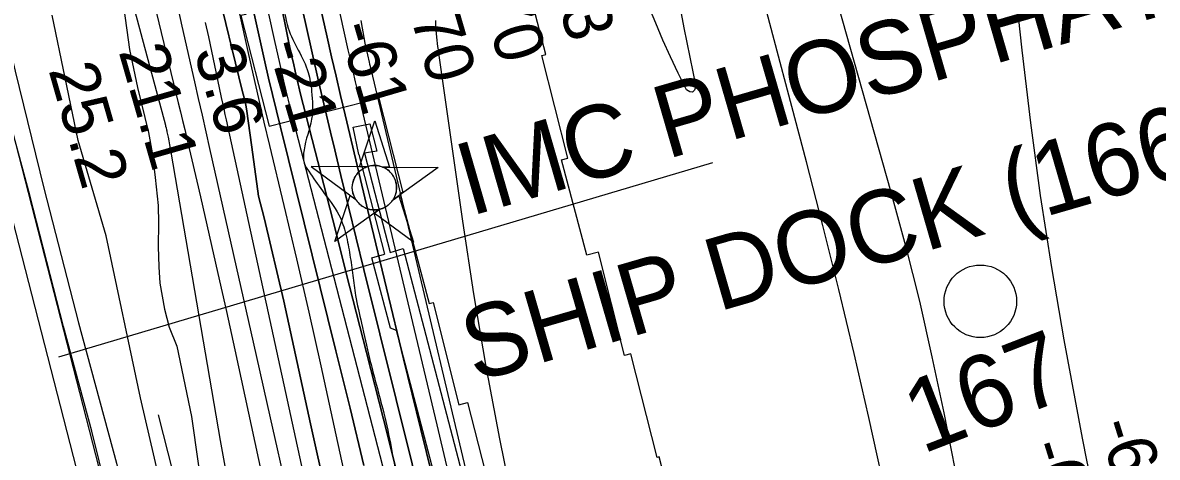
# Model space of a CAD drawing. Extents: x 3405885 to 3443815, y 558517 to 583997.
# Drawn here: x 3413052 to 3414615, y 578768 to 579366 of the extents above; entities that cross this region are included whole.
import ezdxf

# ---------------------------------------------------------------- set-up
doc = ezdxf.new("R2010")
doc.units = 0
for name, color, linetype in [('V-CHAN-DOCK', 7, 'Continuous'), ('V-CHAN-NAID', 7, 'Continuous'), ('V-FLOD-BASE', 7, 'Continuous'), ('V-LEVE-TOET', 7, 'Continuous'), ('V-RIVR-EDGE', 7, 'Continuous'), ('V-RIVR-IDEN', 7, 'Continuous'), ('V-RIVR-MILE', 7, 'Continuous'), ('V-RIVR-RANG', 7, 'Continuous'), ('V-RRAP-RVMT', 7, 'Continuous'), ('V-SITE-VEGE', 7, 'Continuous'), ('V-SURV-LINE', 7, 'Continuous'), ('V-TOPO-DPTH', 7, 'Continuous'), ('V-TOPO-MAJR', 7, 'Continuous'), ('V-TOPO-MINR', 7, 'Continuous'), ('V-TOPO-WATR', 7, 'Continuous')]:
    doc.layers.add(name, color=color, linetype=linetype)

msp = doc.modelspace()

# ---------------------------------------------------------------- linework, layer by layer
at = {"layer": 'V-CHAN-DOCK'}
for p, q in [((3413515.1, 579185), (3413550.3, 579047.6)), ((3413523, 579186.4), (3413558, 579049.8))]:
    msp.add_line(p, q, dxfattribs=at)
for points in [[(3413515.1, 579185), (3413507.4, 579222.2), (3413530.3, 579227.2), (3413539.7, 579189.4), (3413523, 579186.4)], [(3413558, 579049.8), (3413576.3, 579055.1), (3413724.6, 578488.5), (3413706.9, 578484.5)], [(3413267, 578487.6), (3413647.8, 578585.7), (3413627.3, 578663.7), (3413637.3, 578674.7), (3413566.8, 578942.3), (3413558.6, 578945.8), (3413532.9, 579042.5), (3413550.3, 579047.6)]]:
    msp.add_lwpolyline(points, dxfattribs=at)
at = {"layer": 'V-CHAN-NAID'}
for points in [[(3413525.6, 579167.6), (3413516.1, 579167.7), (3413537.2, 579231.2), (3413557.4, 579167.4), (3413547.8, 579167.5), (3413546.2, 579168), (3413544.1, 579168.7), (3413542.1, 579169.1), (3413540.1, 579169.4), (3413538.9, 579169.5), (3413537.4, 579169.6), (3413535.6, 579169.6), (3413534.3, 579169.5), (3413532.4, 579169.3), (3413531, 579169.1), (3413529.2, 579168.7), (3413527.7, 579168.3), (3413526.7, 579168)], [(3413525.6, 579167.6), (3413449.2, 579168.2), (3413510.7, 579122.8), (3413509.6, 579124.7), (3413508.8, 579126.3), (3413508, 579128.3), (3413507.3, 579130.3), (3413506.9, 579131.6), (3413506.5, 579133.3), (3413506.3, 579134.7), (3413506.1, 579136.3), (3413506, 579138), (3413506, 579139.6), (3413506.1, 579141.7), (3413506.3, 579143.3), (3413506.7, 579145.5), (3413507.2, 579147.4), (3413507.8, 579149.3), (3413508.4, 579151), (3413509.1, 579152.6), (3413510, 579154.1), (3413511, 579155.9), (3413512, 579157.3), (3413513, 579158.6), (3413514.1, 579159.8), (3413515.4, 579161.1), (3413516.4, 579162.1), (3413518.1, 579163.5), (3413519.3, 579164.3), (3413521, 579165.4), (3413522.8, 579166.3), (3413524.2, 579167)], [(3413547.8, 579167.5), (3413624.3, 579166.9), (3413562.1, 579122.4), (3413563, 579123.9), (3413564, 579125.7), (3413564.7, 579127.3), (3413565.5, 579129.3), (3413566, 579131.1), (3413566.4, 579132.7), (3413566.8, 579134.7), (3413566.9, 579136.3), (3413567.1, 579138.5), (3413567, 579140.5), (3413566.8, 579142.8), (3413566.6, 579144.5), (3413566.1, 579146.8), (3413565.5, 579148.9), (3413564.7, 579150.9), (3413564.1, 579152.3), (3413563, 579154.2), (3413562, 579156), (3413560.8, 579157.7), (3413559.5, 579159.2), (3413558.2, 579160.6), (3413556.6, 579162.1), (3413554.9, 579163.5), (3413553.2, 579164.7), (3413551.3, 579165.8), (3413549.8, 579166.6)], [(3413544.1, 579109.5), (3413481.9, 579065), (3413503, 579128.4), (3413510.7, 579122.8), (3413511.4, 579121.8), (3413512.7, 579119.9), (3413513.9, 579118.5), (3413515.4, 579117), (3413516.8, 579115.8), (3413518.3, 579114.6), (3413519.7, 579113.6), (3413521.3, 579112.6), (3413523.1, 579111.7), (3413524.8, 579110.9), (3413526.3, 579110.3), (3413527.9, 579109.8), (3413530.1, 579109.2), (3413531.7, 579108.9), (3413533.7, 579108.7), (3413535.2, 579108.6), (3413537.1, 579108.5), (3413538.8, 579108.6), (3413540.5, 579108.8), (3413542.4, 579109.1)], [(3413562.1, 579122.4), (3413569.9, 579128), (3413590.1, 579064.2), (3413536.3, 579103.9), (3413544.1, 579109.5), (3413545.7, 579110), (3413547.4, 579110.5), (3413549.5, 579111.4), (3413551.2, 579112.3), (3413553.1, 579113.4), (3413554.9, 579114.6), (3413556.4, 579115.9), (3413557.7, 579117.1), (3413559.1, 579118.5), (3413560.3, 579119.9), (3413561.4, 579121.4)]]:
    msp.add_lwpolyline(points, close=True, dxfattribs=at)
msp.add_circle((3413536.5, 579139.1), 30.5, dxfattribs=at)
at = {"layer": 'V-FLOD-BASE'}
msp.add_lwpolyline([(3413465.8, 577560.7), (3413432.4, 577685.7), (3413392.9, 577856.9), (3413362.4, 577972.1), (3413330.7, 578093.7), (3413298, 578218.3), (3413261.7, 578356.5), (3413239.3, 578440.4), (3413213.9, 578520.8), (3413187.5, 578640.5), (3413147.2, 578803.6), (3413108.1, 578947.7), (3413061.5, 579129), (3413012.6, 579309.2), (3412974.9, 579462.8), (3412927.8, 579646.5), (3412885.9, 579814.8), (3412853.9, 579977.7), (3412809.2, 580169), (3412768.3, 580316.1)], dxfattribs=at)
at = {"layer": 'V-LEVE-TOET'}
msp.add_lwpolyline([(3412767.9, 580481), (3412806.4, 580341.6), (3412860.6, 580143.7), (3412871.5, 580101.8), (3412901.2, 579957.1), (3412913, 579869.8), (3412926, 579791.3), (3412952.9, 579666.1), (3412992.6, 579509), (3413041.3, 579299.4), (3413080.9, 579138.2), (3413128.6, 578952.8), (3413181, 578759.6), (3413225.8, 578579.5), (3413232.6, 578542.3)], dxfattribs=at)
at = {"layer": 'V-RIVR-EDGE'}
msp.add_spline([(3412820.9, 582098.3), (3412817.8, 582058), (3412815.6, 582029.5), (3412817.7, 582007.9), (3412825.7, 581980.1), (3412850.3, 581879.9), (3412863.7, 581832.7), (3412872, 581799.1), (3412892.3, 581722.3), (3412903.2, 581678.4), (3412909.6, 581634.8), (3412920.5, 581599), (3412934, 581569.3), (3412943.4, 581548.5), (3412954.7, 581511.2), (3412955.3, 581484.9), (3412959.7, 581464), (3412965.1, 581459.6), (3412977.9, 581445), (3412992.4, 581409.1), (3413006.5, 581353.1), (3413015.2, 581302.3), (3413018.7, 581260.3), (3413013.9, 581236.1), (3413008.8, 581220.1), (3413005.1, 581206.5), (3413003.6, 581194.5), (3413004.7, 581180.2), (3413009.3, 581149.1), (3413020.6, 581117.3), (3413042, 581073), (3413073, 581031.3), (3413081, 581018.1), (3413088.7, 580999.8), (3413094.4, 580977.9), (3413100.2, 580939.1), (3413102.7, 580912), (3413106.3, 580894.1), (3413113.5, 580861.9), (3413124.8, 580824.3), (3413140, 580781.4), (3413146.5, 580756.9), (3413148.7, 580740.1), (3413153.8, 580721.8), (3413161, 580692.6), (3413184.2, 580615.7), (3413194, 580582.5), (3413204.2, 580568.2), (3413207.8, 580561.6), (3413214, 580535.3), (3413232.1, 580461.7), (3413244, 580397.7), (3413253, 580345.1), (3413251.9, 580330.8), (3413256.4, 580258.4), (3413262.5, 580217.5), (3413264.6, 580175.4), (3413271.5, 580146.5), (3413278.7, 580117.3), (3413280.2, 580104.8), (3413276.4, 580060.6), (3413276.3, 580025.9), (3413275.6, 580012.4), (3413275.5, 580006.1), (3413277.7, 580003.2), (3413288, 580000.6), (3413298.6, 579998.4), (3413303.7, 579992.2), (3413305.5, 579985.2), (3413310.1, 579953.8), (3413314.5, 579931.1), (3413321, 579914.6), (3413327.2, 579894.5), (3413327.1, 579868.9), (3413323.4, 579842.6), (3413317.9, 579835.3), (3413316, 579824.7), (3413315.6, 579806.5), (3413320, 579780.1), (3413328, 579765.1), (3413335.6, 579758.2), (3413338.2, 579753.4), (3413338.9, 579747.5), (3413338.9, 579742.8), (3413335.5, 579730.7), (3413330.8, 579723.1), (3413327.8, 579714.3), (3413325.2, 579701.2), (3413326.7, 579689.5), (3413332.1, 579675.9), (3413338.3, 579668.2), (3413342.7, 579666.4), (3413352.6, 579666.7), (3413357.3, 579663.4), (3413365.3, 579652.4), (3413371.9, 579635.2), (3413374.8, 579618.4), (3413377.6, 579592.5), (3413379.4, 579557.4), (3413373.8, 579521.6), (3413375.2, 579501.1), (3413382.1, 579476.9), (3413395.1, 579440), (3413408.6, 579400.8), (3413417.6, 579358.8), (3413445.2, 579297.7), (3413449.9, 579271.7), (3413449.8, 579233.3), (3413439.5, 579191.3), (3413438.7, 579182.2), (3413439.8, 579172.7), (3413446, 579161.7), (3413464.9, 579134.6), (3413487.5, 579101.6), (3413497, 579074.9), (3413502.7, 579046.4), (3413506.7, 579018.2), (3413510.6, 578990.8), (3413518.6, 578952.4), (3413529.8, 578903.8), (3413538.1, 578871.6), (3413547.9, 578834.6), (3413558.4, 578787.4), (3413566.7, 578743.2), (3413574.6, 578699.3), (3413585.1, 578637.1), (3413595.2, 578577.2), (3413599.5, 578547.5), (3413610.7, 578516.1), (3413620.2, 578504), (3413626, 578499.2), (3413635.5, 578497), (3413635.9, 578494.4), (3413634.1, 578490.1), (3413632.2, 578487.1), (3413632.2, 578479.5), (3413633.2, 578455), (3413642.2, 578391), (3413644.3, 578359.2), (3413649, 578338.7), (3413656.3, 578322.2), (3413667.6, 578313.8), (3413676, 578309), (3413684.4, 578305.3), (3413688.8, 578300.2), (3413697.9, 578288.5), (3413702.2, 578272.4), (3413709.1, 578250.8), (3413714.9, 578233.2), (3413728.7, 578187.2), (3413734.8, 578151.3), (3413738.8, 578114.4), (3413740.5, 578084), (3413746.7, 578059.2), (3413750.7, 578043.4), (3413751.3, 578020), (3413747.6, 577990.8), (3413742, 577955), (3413736.9, 577934.5), (3413735.4, 577919.6), (3413733.5, 577904.2), (3413737.1, 577880.1), (3413741.4, 577864.7), (3413741.4, 577863.2), (3413750.2, 577865.8), (3413755, 577862.8), (3413760, 577845.7), (3413773.8, 577798.1), (3413781.8, 577765.2), (3413793, 577724.9), (3413797, 577700.4), (3413803.4, 577637.2), (3413804.4, 577613.8), (3413807.7, 577591.8), (3413815.3, 577561.1), (3413829.4, 577524.9), (3413841.8, 577493.8), (3413853.8, 577466), (3413863.2, 577445.5), (3413869.8, 577431.2), (3413869.8, 577426.1), (3413869.7, 577412.9), (3413868.9, 577389.5), (3413869.2, 577353), (3413871, 577339.8), (3413873.9, 577328.5), (3413883, 577306.5), (3413889.5, 577287.9), (3413905.1, 577244.3), (3413913.5, 577211), (3413925.4, 577161.3), (3413947.6, 577101.7), (3413958.8, 577073.5), (3413969, 577057.4), (3413973, 577043.8), (3413979.9, 577014.6), (3414002, 576930.8), (3414004.5, 576907.4), (3414006.3, 576897.2), (3414015, 576880.3), (3414024.5, 576858.8), (3414031.3, 576835.7), (3414040.8, 576799.5), (3414054.2, 576750.1), (3414062.5, 576713.9), (3414069.3, 576679.9), (3414074.4, 576668.5), (3414075.1, 576663.4), (3414103.1, 576586.2), (3414107.4, 576564.6), (3414115.4, 576529.2), (3414119, 576508), (3414142.2, 576433.7), (3414153.5, 576399.3), (3414159.6, 576378.5), (3414164.7, 576348.8), (3414174.1, 576303.8), (3414178, 576275), (3414184.1, 576248.3), (3414191.1, 576234), (3414204.1, 576202.1), (3414212.1, 576179.5), (3414243, 576089.5), (3414264.8, 576025.4), (3414269.5, 576005.7), (3414269.4, 575994.4), (3414267.6, 575989.1)], degree=3, dxfattribs=at)
at = {"layer": 'V-RIVR-MILE'}
msp.add_circle((3414371.4, 578982.6), 50, dxfattribs=at)
at = {"layer": 'V-RIVR-RANG'}
msp.add_line((3413101.6, 578906), (3414002.6, 579173.9), dxfattribs=at)
at = {"layer": 'V-RRAP-RVMT'}
for points in [[(3413113.3, 580352.9), (3413130.9, 580232.1), (3413110.9, 580229.3), (3413132.9, 580079.4), (3413115.1, 580075.8), (3413143.9, 579932.2), (3413132.9, 579930.1), (3413162.8, 579777.1), (3413165.6, 579777.6), (3413194.6, 579633.9), (3413200, 579635), (3413229.1, 579491.8), (3413325, 579511.4), (3413341.4, 579447.3), (3413441.1, 579472.8), (3413451.2, 579433.2), (3413351.8, 579407), (3413359.3, 579377.6), (3413352.6, 579376), (3413391.4, 579223.8), (3413542.6, 579262.3), (3413575.6, 579132.6)], [(3413803, 579179.7), (3413767, 579320.9), (3413772.6, 579322.3), (3413733.3, 579474.4), (3413717.6, 579470.3), (3413688.3, 579584), (3413727.7, 579592), (3413696.4, 579745.4), (3413681.1, 579742.3), (3413652.2, 579885.5), (3413624, 579880), (3413596.2, 580022.5), (3413563.4, 580016.3), (3413534.8, 580159.2), (3413519.8, 580156.2), (3413500.9, 580285.6)], [(3413993.1, 578375.8), (3413970.6, 578464.8), (3414002.6, 578473), (3413965.8, 578615.9), (3413968.5, 578616.6), (3413929, 578768.5), (3413926.3, 578767.7), (3413889.9, 578910.4), (3413880.9, 578908.1), (3413845.2, 579050.3), (3413829.2, 579046.3), (3413794.4, 579177.6), (3413803, 579179.7)], [(3413575.6, 579132.6), (3413571.6, 579131.6), (3413611.8, 578979.7), (3413617.4, 578981.1), (3413652.8, 578840.1), (3413664.8, 578843.1), (3413699.3, 578708.7), (3413688.9, 578706.1), (3413728, 578555.6), (3413730.8, 578556.3), (3413767.7, 578413.3), (3413769.5, 578413.8), (3413778.5, 578378.1)]]:
    msp.add_lwpolyline(points, dxfattribs=at)
at = {"layer": 'V-SITE-VEGE'}
for points in [[(3413185.3, 579429.3), (3413198.8, 579329.5), (3413210.2, 579277), (3413225.1, 579214.9), (3413230.3, 579187.2), (3413234.2, 579153), (3413238.6, 579114.6), (3413239.1, 579090.4), (3413238.3, 579058), (3413239.3, 579030.2), (3413240.9, 579007.8), (3413247.1, 578971.8), (3413253.5, 578947), (3413264.2, 578920.7), (3413284.2, 578823.9), (3413302.8, 578694.6)], [(3413252.6, 578683.7), (3413214.1, 578849.7), (3413166.7, 579073), (3413128, 579204.1), (3413092.6, 579376.6)]]:
    msp.add_lwpolyline(points, dxfattribs=at)
at = {"layer": 'V-SURV-LINE'}
for points in [[(3412864.6, 579889.2), (3413603.1, 577015.1)], [(3413574.1, 577007.7), (3412835.6, 579881.8)]]:
    msp.add_lwpolyline(points, dxfattribs=at)
at = {"layer": 'V-TOPO-DPTH'}
for points in [[(3413113.8, 580487.8), (3413186.9, 580114.7), (3413203.7, 580017.6), (3413234.8, 579843), (3413255.8, 579718.6), (3413318.1, 579422.2), (3413354.3, 579273.1), (3413358.5, 579257.7), (3413360.2, 579247.5), (3413367.7, 579194.7), (3413376.9, 579127.4), (3413384.5, 579097.6), (3413411.5, 578982.6), (3413448.5, 578813.9), (3413532.7, 578434.8), (3413535.3, 578425.5), (3413536.9, 578418.7), (3413621.2, 578042.1), (3413698.7, 577706.5), (3413704.6, 577683.5), (3413708.8, 577666.4), (3413718.9, 577631.5), (3413770.4, 577445.8)], [(3413770.4, 577445.8), (3413718.9, 577631.5), (3413708.8, 577666.4), (3413704.6, 577683.5), (3413698.7, 577706.5), (3413621.2, 578042.1), (3413536.9, 578418.7), (3413535.3, 578425.5), (3413532.7, 578434.8), (3413448.5, 578813.9), (3413411.5, 578982.6), (3413384.5, 579097.6), (3413376.9, 579127.4), (3413367.7, 579194.7), (3413360.2, 579247.5), (3413358.5, 579257.7), (3413354.3, 579273.1), (3413318.1, 579422.2), (3413255.8, 579718.6), (3413234.8, 579843), (3413203.7, 580017.6), (3413186.9, 580114.7), (3413113.8, 580487.8)], [(3413654.9, 578491), (3413521.9, 579026.6), (3413511.2, 579069.7), (3413500.7, 579112.9), (3413490.3, 579156), (3413479.9, 579199.2), (3413477.9, 579207.8), (3413468.7, 579246.8), (3413459.6, 579285.7), (3413450.6, 579324.7), (3413441.8, 579363.7), (3413402.4, 579539.5)], [(3413654.9, 578491), (3413521.9, 579026.6), (3413511.2, 579069.7), (3413500.7, 579112.9), (3413490.3, 579156), (3413479.9, 579199.2), (3413477.9, 579207.8), (3413468.7, 579246.8), (3413459.6, 579285.7), (3413450.6, 579324.7), (3413441.8, 579363.7), (3413402.4, 579539.5)], [(3413451.1, 579436.2), (3413471.4, 579346.2), (3413477.5, 579319.4), (3413483.6, 579292.7), (3413489.8, 579266), (3413496.1, 579239.3), (3413529.8, 579098), (3413553.1, 579000.7), (3413576.5, 578903.4), (3413600.2, 578806.2), (3413624.1, 578709)], [(3413451.1, 579436.2), (3413471.4, 579346.2), (3413477.5, 579319.4), (3413483.6, 579292.7), (3413489.8, 579266), (3413496.1, 579239.3), (3413529.8, 579098), (3413553.1, 579000.7), (3413576.5, 578903.4), (3413600.2, 578806.2), (3413624.1, 578709)], [(3413257.9, 579422.9), (3413271.3, 579361.6), (3413288.5, 579285), (3413293.7, 579262.1), (3413298.9, 579239.1), (3413304.1, 579216.2), (3413309.2, 579193.2), (3413346.1, 579030.2), (3413369.5, 578926.3), (3413392.9, 578822.3), (3413416.2, 578718.3)], [(3413369, 579386.8), (3413385.6, 579312.3), (3413390.7, 579289.8), (3413396, 579267.3), (3413401.4, 579244.8), (3413406.9, 579222.4), (3413483.5, 578914.5), (3413502.9, 578835.6), (3413521.7, 578756.6)], [(3413521.7, 578756.6), (3413502.9, 578835.6), (3413483.5, 578914.5), (3413406.9, 579222.4), (3413401.4, 579244.8), (3413396, 579267.3), (3413390.7, 579289.8), (3413385.6, 579312.3), (3413369, 579386.8)], [(3413571.9, 578728.8), (3413548.8, 578820.3), (3413525.6, 578911.9), (3413502.3, 579003.4), (3413479, 579094.9), (3413434.2, 579269.8), (3413433.2, 579273.8), (3413432.2, 579277.8), (3413431.3, 579281.8), (3413430.4, 579285.8), (3413427.3, 579299.5), (3413424.8, 579310.4), (3413422.4, 579321.2), (3413420.1, 579332.1), (3413417.8, 579343), (3413413.9, 579361.6), (3413409.7, 579381.8)], [(3413409.7, 579381.8), (3413413.9, 579361.6), (3413417.8, 579343), (3413420.1, 579332.1), (3413422.4, 579321.2), (3413424.8, 579310.4), (3413427.3, 579299.5), (3413430.4, 579285.8), (3413431.3, 579281.8), (3413432.2, 579277.8), (3413433.2, 579273.8), (3413434.2, 579269.8), (3413479, 579094.9), (3413502.3, 579003.4), (3413525.6, 578911.9), (3413548.8, 578820.3), (3413571.9, 578728.8)]]:
    msp.add_lwpolyline(points, dxfattribs=at)
at = {"layer": 'V-TOPO-MAJR'}
for points in [[(3413636.4, 578755.9), (3413622.9, 578812.3), (3413514.1, 579270.1), (3413510.6, 579284.8), (3413507.2, 579299.5), (3413503.8, 579314.3), (3413500.4, 579329), (3413489.1, 579379.1)], [(3413238.4, 578826.1), (3413353.1, 578375.1), (3413354.3, 578370.5), (3413355.4, 578365.8), (3413356.5, 578361.2), (3413357.6, 578356.6), (3413380.9, 578257.2)]]:
    msp.add_lwpolyline(points, dxfattribs=at)
at = {"layer": 'V-TOPO-MINR'}
for points in [[(3413081.9, 579844.7), (3413248.5, 579225.2), (3413248.6, 579224.6), (3413248.8, 579224), (3413249.3, 579221.7), (3413250, 579218.8), (3413250.3, 579217.4), (3413250.6, 579216), (3413252.1, 579208.5), (3413253.1, 579203.4), (3413254, 579198.2), (3413255, 579193), (3413255.9, 579187.9), (3413324.1, 578791), (3413336.3, 578722.5), (3413349.2, 578654.1), (3413362.9, 578585.9), (3413377.2, 578517.8), (3413398.9, 578417.7), (3413402.8, 578399.7), (3413406.7, 578381.8), (3413410.7, 578363.8), (3413414.8, 578345.8), (3413553.9, 577728.2)], [(3413402.4, 579539.5), (3413441.8, 579363.7), (3413450.6, 579324.7), (3413459.6, 579285.7), (3413468.7, 579246.8), (3413477.9, 579207.8), (3413479.9, 579199.2), (3413490.3, 579156), (3413500.7, 579112.9), (3413511.2, 579069.7), (3413521.9, 579026.6), (3413654.9, 578491)], [(3414670.3, 578258.6), (3414544, 578664.7), (3414534.7, 578696.7), (3414526.2, 578728.9), (3414518.8, 578761.4), (3414512.1, 578794), (3414487, 578929.7), (3414469.8, 579029), (3414454.2, 579128.5), (3414440.8, 579228.4), (3414428.9, 579328.5), (3414408, 579523.3)], [(3413206.2, 579503.2), (3413266.2, 579255.8), (3413269.1, 579243.6), (3413272.1, 579231.4), (3413275, 579219.2), (3413277.8, 579206.9), (3413296.7, 579126.3), (3413308.9, 579073.7), (3413320.9, 579021.1), (3413332.6, 578968.4), (3413344.1, 578915.7), (3413440.4, 578469.1)], [(3414158.6, 579450.7), (3414247.8, 579134.7), (3414268.2, 579058.8), (3414287.4, 578982.6), (3414304.8, 578906), (3414321, 578829.1), (3414341.3, 578726.3)], [(3413339.1, 579430.7), (3413362.1, 579326.4), (3413369.3, 579294), (3413376.6, 579261.7), (3413384.2, 579229.3), (3413391.8, 579197), (3413411.5, 579114.6), (3413428.9, 579041.1), (3413446, 578967.5), (3413462.6, 578893.7), (3413478.9, 578820), (3413557.8, 578457.3)], [(3413624.1, 578709), (3413600.2, 578806.2), (3413576.5, 578903.4), (3413553.1, 579000.7), (3413529.8, 579098), (3413496.1, 579239.3), (3413489.8, 579266), (3413483.6, 579292.7), (3413477.5, 579319.4), (3413471.4, 579346.2), (3413451.1, 579436.2)], [(3413257.9, 579422.9), (3413271.3, 579361.6), (3413288.5, 579285), (3413293.7, 579262.1), (3413298.9, 579239.1), (3413304.1, 579216.2), (3413309.2, 579193.2), (3413346.1, 579030.2), (3413369.5, 578926.3), (3413392.9, 578822.3), (3413416.2, 578718.3)], [(3414246.6, 578691.1), (3414217.6, 578822.4), (3414197.4, 578910.8), (3414176.6, 578999), (3414154.6, 579086.9), (3414132, 579174.6), (3414067.2, 579419.3)], [(3413369, 579386.8), (3413385.6, 579312.3), (3413390.7, 579289.8), (3413396, 579267.3), (3413401.4, 579244.8), (3413406.9, 579222.4), (3413483.5, 578914.5), (3413502.9, 578835.6), (3413521.7, 578756.6)], [(3413956.3, 579393.5), (3413963, 579359.3), (3413979.2, 579278.5), (3413977.4, 579273.4), (3413974.8, 579270.6), (3413971, 579271.2), (3413966.4, 579274), (3413955.2, 579296.6), (3413944.4, 579319.4), (3413934.1, 579342.4), (3413924.1, 579365.6), (3413910.4, 579398.6)], [(3413390.4, 579378.6), (3413398.3, 579343.2), (3413408.3, 579298.8), (3413411.3, 579285.7), (3413414.4, 579272.6), (3413417.7, 579259.6), (3413421, 579246.5), (3413600.2, 578552)], [(3413409.7, 579381.8), (3413413.9, 579361.6), (3413417.8, 579343), (3413420.1, 579332.1), (3413422.4, 579321.2), (3413424.8, 579310.4), (3413427.3, 579299.5), (3413430.4, 579285.8), (3413431.3, 579281.8), (3413432.2, 579277.8), (3413433.2, 579273.8), (3413434.2, 579269.8), (3413479, 579094.9), (3413502.3, 579003.4), (3413525.6, 578911.9), (3413548.8, 578820.3), (3413571.9, 578728.8)], [(3413517.8, 579369.3), (3413519.5, 579358.8), (3413520.4, 579353.8), (3413521.9, 579345.9), (3413523.4, 579337.9), (3413525.1, 579330), (3413526.8, 579322.1), (3413529.1, 579312.1), (3413529.7, 579309.2), (3413530.4, 579306.3), (3413531.1, 579303.4), (3413531.8, 579300.4), (3413719, 578510.9)], [(3413620.6, 579369.5), (3413620.7, 579366), (3413620.8, 579362.6), (3413621, 579359.1), (3413621.3, 579355.7), (3413622.6, 579342.3), (3413623.1, 579337.8), (3413623.6, 579333.3), (3413624.2, 579328.8), (3413624.8, 579324.3), (3413657.7, 579093.1), (3413673.1, 578992.7), (3413689.9, 578892.7), (3413708.8, 578793), (3413729.1, 578693.5)], [(3413303.4, 579366.7), (3413307.6, 579346.8), (3413311.8, 579327), (3413316, 579307.2), (3413320.2, 579287.4), (3413325.4, 579263.4), (3413327.1, 579255.6), (3413328.8, 579247.8), (3413330.5, 579240), (3413332.2, 579232.3), (3413442.5, 578726.4)]]:
    msp.add_lwpolyline(points, dxfattribs=at)
at = {"layer": 'V-TOPO-WATR'}
msp.add_lwpolyline([(3413770.4, 577445.8), (3413718.9, 577631.5), (3413708.8, 577666.4), (3413704.6, 577683.5), (3413698.7, 577706.5), (3413621.2, 578042.1), (3413536.9, 578418.7), (3413535.3, 578425.5), (3413532.7, 578434.8), (3413448.5, 578813.9), (3413411.5, 578982.6), (3413384.5, 579097.6), (3413376.9, 579127.4), (3413367.7, 579194.7), (3413360.2, 579247.5), (3413358.5, 579257.7), (3413354.3, 579273.1), (3413318.1, 579422.2), (3413255.8, 579718.6), (3413234.8, 579843), (3413203.7, 580017.6), (3413186.9, 580114.7), (3413113.8, 580487.8)], dxfattribs=at)

# ---------------------------------------------------------------- texts
at = {"layer": 'V-CHAN-NAID'}
for s, p in [('IMC PHOSPHATES FAUSTINA ', (3413668.2, 579099.5)), (' SHIP DOCK (166.9) (3)', (3413638.9, 578860.5))]:
    msp.add_text(s, height=100, rotation=16.1722, dxfattribs=at).set_placement(p)
at = {"layer": 'V-RIVR-IDEN'}
msp.add_text('167', height=100, rotation=21.0973, dxfattribs=at).set_placement((3414291.3, 578771.9))
at = {"layer": 'V-RIVR-RANG'}
for s, rotation, p in [('-73', 286.3115, (3413769.1, 579460.8)), ('-70', 286.3115, (3413673.7, 579430.7)), ('-70', 286.3115, (3413577.7, 579402.8)), ('-61', 286.3115, (3413485.9, 579360.3)), ('21.1', 286.0283, (3413183.7, 579326.9)), ('3.6', 286.3115, (3413287.4, 579326.6)), ('-21', 286.3115, (3413389, 579335.5)), ('25.2', 286.0283, (3413087, 579301.4)), ('-64', 287.3766, (3414532.7, 578812.7)), ('-69', 287.3766, (3414437.2, 578783.1))]:
    msp.add_text(s, height=67, rotation=rotation, dxfattribs=at).set_placement(p)

doc.saveas('drawing.dxf')
